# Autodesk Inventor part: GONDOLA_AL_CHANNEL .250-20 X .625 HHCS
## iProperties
Shininess: 64.0
Length Units: 11272
Angle Units: 11279
Time Units: 11290
Mass Units: 11286
Length Display Precision: 3
Angle Display Precision: 2
Compacted: True
Part Number: GONDOLA_AL_CHANNEL .250-20 X .625 HHCS
Document SubType Name: Modeling
Created: 2004-08
Designer: John Blackburn
Manufacturer: Standard
Standards Organization: Custom
Material: Stainless Steel, Austenitic
Density: 0.0
Volumn: 0.0
Area: 0.0
PropertySet Name: Model Information
Control State: 0
Master: False
Checked Out: False
Author: John Blackburn
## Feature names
1. Base1
2. ExtrusionBlind1
3. Chamfer1
